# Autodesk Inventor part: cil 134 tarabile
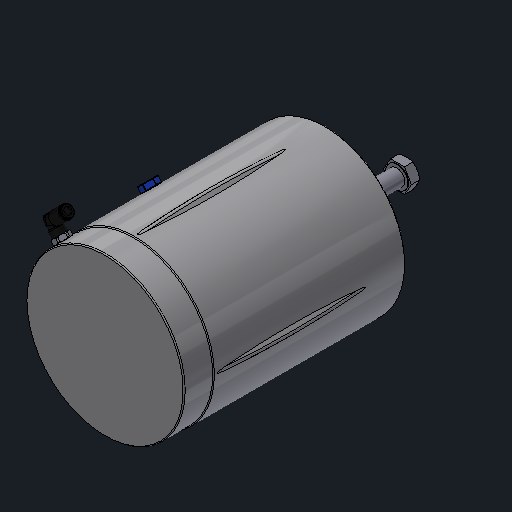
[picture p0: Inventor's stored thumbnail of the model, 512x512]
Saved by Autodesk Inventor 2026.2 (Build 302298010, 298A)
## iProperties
Created: 2026-03
Part Number: cil 134 tarabile
Material: Generico
Document SubType Name: Modeling
Designer: marz-m
Density: 1 g/cm^3
Appearance: Default
Author: marz-m
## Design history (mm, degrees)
feature "Base1"
node "Solido1"
